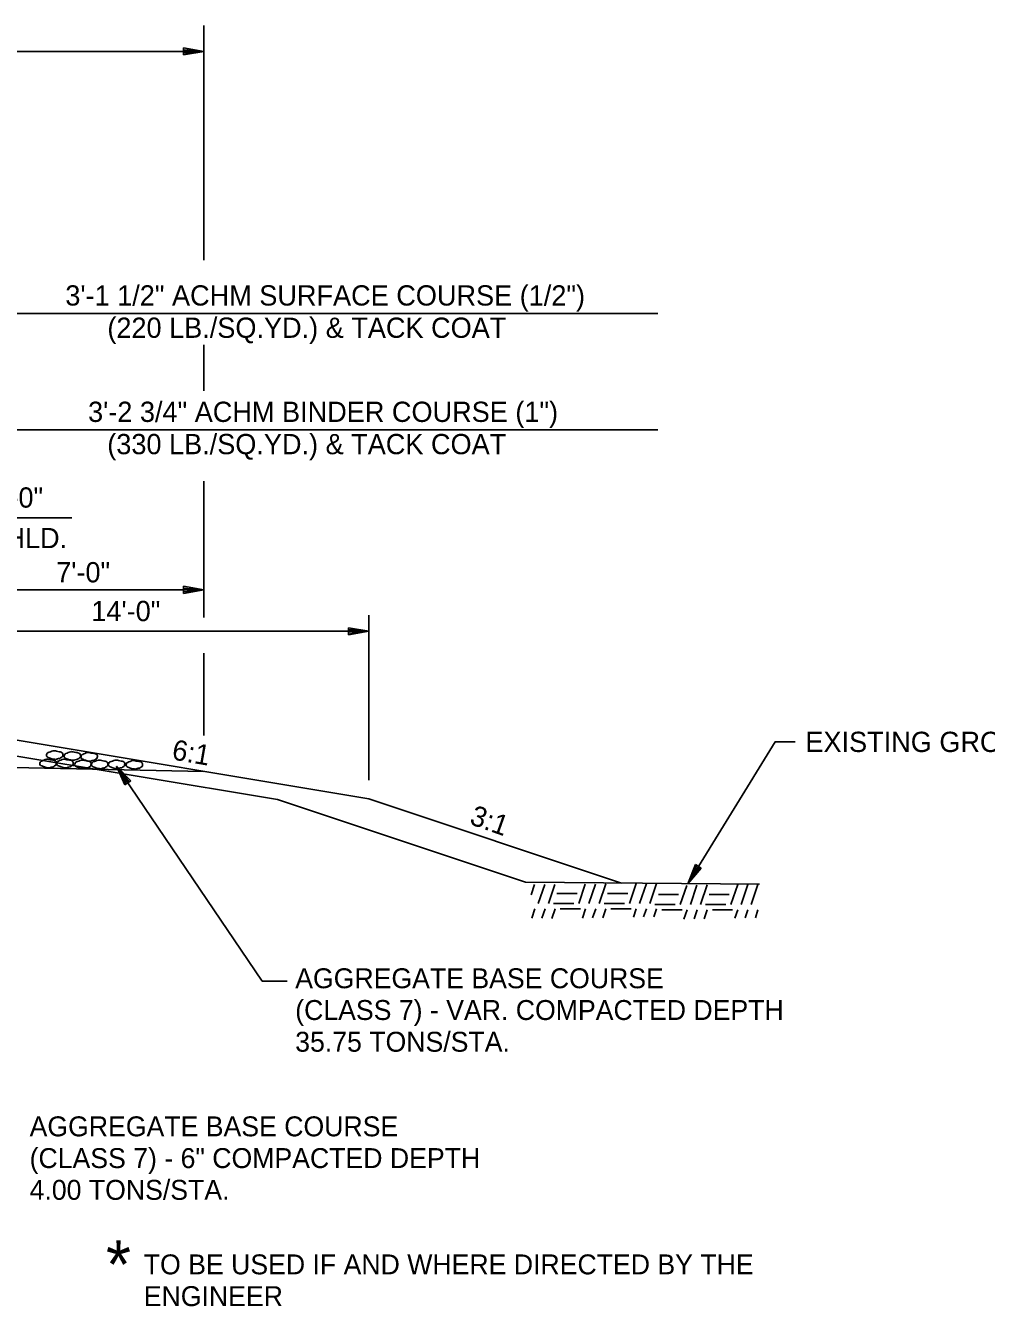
# Model space of a CAD drawing. Extents: x 1461570 to 1461697, y 1686711 to 1686957.
# Drawn here: x 1461621.58 to 1461650.03, y 1686769.49 to 1686807.42 of the extents above; entities that cross this region are included whole.
import ezdxf

# ---------------------------------------------------------------- set-up
doc = ezdxf.new("R2010")
doc.units = 0
for name, color, linetype in [('1', 7, 'Continuous'), ('10', 7, 'Continuous'), ('19', 7, 'Continuous'), ('20', 7, 'Continuous'), ('42', 7, 'Continuous'), ('Default', 7, 'Continuous'), ('Level 9', 7, 'Continuous'), ('R_Draft', 7, 'Continuous')]:
    doc.layers.add(name, color=color, linetype=linetype)

# ---------------------------------------------------------------- blocks, each defined once
blk = doc.blocks.new('ROCKS')
at = {"layer": '1'}
blk.add_spline([(0.013, 0.06), (0.053, 0.053), (0.107, 0.033), (0.133, 0.013), (0.133, -0.007), (0.12, -0.033), (0.107, -0.04), (0.073, -0.053), (0.033, -0.067), (0.013, -0.067), (-0.02, -0.06), (-0.06, -0.053), (-0.087, -0.047), (-0.113, -0.02), (-0.113, -0.007), (-0.107, 0.02), (-0.087, 0.033), (-0.067, 0.047), (-0.033, 0.053), (-0.02, 0.06), (0.013, 0.06)], degree=3, dxfattribs=at)

msp = doc.modelspace()

# ---------------------------------------------------------------- linework, layer by layer
at = {"layer": '19'}
for p, q in [((1461626.253, 1686790.605), (1461626.253, 1686790.815)), ((1461626.253, 1686790.815), (1461626.853, 1686790.71)), ((1461626.253, 1686790.76), (1461626.693, 1686790.725)), ((1461626.853, 1686790.71), (1461626.253, 1686790.605)), ((1461626.693, 1686790.695), (1461626.253, 1686790.655)), ((1461619.738, 1686786.521), (1461631.738, 1686784.521)), ((1461616.654, 1686785.539), (1461626.853, 1686785.335)), ((1461628.584, 1686779.122), (1461624.268, 1686785.492)), ((1461624.513, 1686784.936), (1461624.268, 1686785.492)), ((1461624.268, 1686785.492), (1461624.688, 1686785.051)), ((1461624.554, 1686784.964), (1461624.343, 1686785.35)), ((1461624.366, 1686785.366), (1461624.642, 1686785.024)), ((1461624.688, 1686785.051), (1461624.513, 1686784.936)), ((1461639.219, 1686782.027), (1461631.738, 1686784.521)), ((1461641.186, 1686782.01), (1461641.41, 1686782.576)), ((1461641.587, 1686782.467), (1461641.186, 1686782.01)), ((1461641.26, 1686782.151), (1461641.453, 1686782.544)), ((1461641.547, 1686782.488), (1461641.283, 1686782.139)), ((1461641.41, 1686782.576), (1461641.587, 1686782.467)), ((1461636.377, 1686782.052), (1461643.307, 1686781.991)), ((1461629.321, 1686779.122), (1461628.584, 1686779.122))]:
    msp.add_line(p, q, dxfattribs=at)
msp.add_lwpolyline([(1461644.369, 1686786.209), (1461643.769, 1686786.209), (1461641.186, 1686782.01)], dxfattribs=at)
at = {"layer": '20'}
for p, q in [((1461626.853, 1686800.472), (1461626.853, 1686807.418)), ((1461586.622, 1686806.655), (1461626.853, 1686806.655)), ((1461626.253, 1686806.76), (1461626.253, 1686806.55)), ((1461626.853, 1686806.655), (1461626.253, 1686806.76)), ((1461626.693, 1686806.67), (1461626.253, 1686806.705)), ((1461626.253, 1686806.55), (1461626.853, 1686806.655)), ((1461626.253, 1686806.6), (1461626.693, 1686806.64)), ((1461619.864, 1686798.892), (1461640.297, 1686798.892)), ((1461626.853, 1686796.602), (1461626.853, 1686797.968)), ((1461619.969, 1686795.446), (1461640.297, 1686795.446)), ((1461626.853, 1686789.893), (1461626.853, 1686793.93)), ((1461631.738, 1686785.076), (1461631.738, 1686789.958)), ((1461631.138, 1686789.589), (1461631.138, 1686789.379)), ((1461631.738, 1686789.484), (1461631.138, 1686789.589)), ((1461631.578, 1686789.499), (1461631.138, 1686789.534)), ((1461631.138, 1686789.379), (1461631.738, 1686789.484)), ((1461631.138, 1686789.429), (1461631.578, 1686789.469)), ((1461626.853, 1686786.399), (1461626.853, 1686788.836))]:
    msp.add_line(p, q, dxfattribs=at)
at = {"layer": '42'}
for p, q in [((1461622.946, 1686792.846), (1461617.732, 1686792.845)), ((1461631.738, 1686789.484), (1461617.738, 1686789.484)), ((1461636.547, 1686781.68), (1461636.649, 1686781.986)), ((1461636.76, 1686781.419), (1461636.948, 1686781.984)), ((1461637.06, 1686781.419), (1461637.247, 1686781.982)), ((1461637.96, 1686781.419), (1461638.151, 1686781.991)), ((1461638.26, 1686781.419), (1461638.453, 1686781.998)), ((1461638.56, 1686781.419), (1461638.755, 1686782.004)), ((1461639.46, 1686781.419), (1461639.66, 1686782.019)), ((1461639.507, 1686782.019), (1461639.51, 1686782.019)), ((1461639.76, 1686781.419), (1461639.96, 1686782.019)), ((1461640.06, 1686781.419), (1461640.26, 1686782.019)), ((1461640.965, 1686781.389), (1461641.156, 1686781.961)), ((1461641.265, 1686781.389), (1461641.458, 1686781.967)), ((1461641.565, 1686781.389), (1461641.76, 1686781.973)), ((1461642.465, 1686781.389), (1461642.665, 1686781.989)), ((1461642.512, 1686781.989), (1461642.515, 1686781.989)), ((1461642.765, 1686781.389), (1461642.965, 1686781.989)), ((1461643.065, 1686781.389), (1461643.265, 1686781.989)), ((1461637.31, 1686781.719), (1461637.91, 1686781.719)), ((1461638.81, 1686781.719), (1461639.41, 1686781.719)), ((1461640.315, 1686781.689), (1461640.915, 1686781.689)), ((1461641.815, 1686781.689), (1461642.415, 1686781.689)), ((1461636.566, 1686780.987), (1461636.66, 1686781.269)), ((1461636.865, 1686780.985), (1461636.96, 1686781.269)), ((1461637.164, 1686780.982), (1461637.26, 1686781.269)), ((1461637.21, 1686781.419), (1461637.81, 1686781.419)), ((1461637.41, 1686781.269), (1461638.01, 1686781.269)), ((1461638.067, 1686780.99), (1461638.16, 1686781.269)), ((1461638.369, 1686780.996), (1461638.46, 1686781.269)), ((1461638.671, 1686781.002), (1461638.76, 1686781.269)), ((1461638.71, 1686781.419), (1461639.31, 1686781.419)), ((1461638.91, 1686781.269), (1461639.46, 1686781.269)), ((1461639.46, 1686781.269), (1461639.51, 1686781.269)), ((1461639.577, 1686781.021), (1461639.66, 1686781.269)), ((1461639.879, 1686781.027), (1461639.96, 1686781.269)), ((1461640.181, 1686781.033), (1461640.26, 1686781.269)), ((1461640.215, 1686781.389), (1461640.815, 1686781.389)), ((1461640.415, 1686781.239), (1461641.015, 1686781.239)), ((1461641.072, 1686780.959), (1461641.165, 1686781.239)), ((1461641.374, 1686780.965), (1461641.465, 1686781.239)), ((1461641.676, 1686780.971), (1461641.765, 1686781.239)), ((1461641.715, 1686781.389), (1461642.315, 1686781.389)), ((1461641.915, 1686781.239), (1461642.465, 1686781.239)), ((1461642.465, 1686781.239), (1461642.515, 1686781.239)), ((1461642.583, 1686780.99), (1461642.665, 1686781.239)), ((1461642.885, 1686780.996), (1461642.965, 1686781.239)), ((1461643.187, 1686781.003), (1461643.265, 1686781.239))]:
    msp.add_line(p, q, dxfattribs=at)
at = {"layer": 'Level 9'}
msp.add_line((1461626.853, 1686790.71), (1461619.738, 1686790.71), dxfattribs=at)
at = {"layer": 'R_Draft'}
for p, q in [((1461629.039, 1686784.498), (1461617.238, 1686786.465)), ((1461636.377, 1686782.052), (1461629.039, 1686784.498))]:
    msp.add_line(p, q, dxfattribs=at)

# ---------------------------------------------------------------- block references
at = {"layer": '1', "xscale": 1.968733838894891, "yscale": 1.968733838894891, "rotation": 180}
for p in [(1461622.263, 1686785.563), (1461622.455, 1686785.813), (1461622.761, 1686785.563), (1461622.98, 1686785.786), (1461623.292, 1686785.537), (1461623.478, 1686785.76), (1461623.791, 1686785.537), (1461624.289, 1686785.537), (1461624.814, 1686785.524)]:
    msp.add_blockref('ROCKS', p, dxfattribs=at)

# ---------------------------------------------------------------- texts
at = {"layer": '10'}
for s, height, rotation, p in [('*', 1.422, 359.9954, (1461623.955, 1686770.026)), ('TO BE USED IF AND WHERE DIRECTED BY THE ', 0.59001, 360, (1461625.075, 1686770.442)), ('ENGINEER', 0.59, 360, (1461625.075, 1686769.502))]:
    msp.add_text(s, height=height, rotation=rotation, dxfattribs=at).set_placement(p)
at = {"layer": '19'}
for s, p in [('2\'-0"', (1461620.497, 1686793.145)), ('SHLD.', (1461620.443, 1686791.945)), ('7\'-0"', (1461622.481, 1686790.932)), ('14\'-0"', (1461623.522, 1686789.784))]:
    msp.add_text(s, height=0.6, dxfattribs=at).set_placement(p)
for s, height, rotation, p in [('6:1', 0.6, 350.1584, (1461625.884, 1686785.694)), ('3:1', 0.6, 340.4943, (1461634.693, 1686783.785)), ('AGGREGATE BASE COURSE', 0.59001, 360, (1461629.56, 1686778.914)), ('(CLASS 7) - VAR. COMPACTED DEPTH', 0.59001, 360, (1461629.56, 1686777.974)), ('35.75 TONS/STA.', 0.59001, 360, (1461629.56, 1686777.034)), ('AGGREGATE BASE COURSE', 0.59001, 360, (1461621.694, 1686774.529)), ('(CLASS 7) - 6" COMPACTED DEPTH', 0.59001, 360, (1461621.694, 1686773.589)), ('4.00 TONS/STA.', 0.59001, 360, (1461621.694, 1686772.649))]:
    msp.add_text(s, height=height, rotation=rotation, dxfattribs=at).set_placement(p)
at = {"layer": 'Default'}
for s, p in [('3\'-1 1/2" ACHM SURFACE COURSE (1/2")', (1461622.752, 1686799.129)), ('(220 LB./SQ.YD.) & TACK COAT', (1461623.997, 1686798.173)), ('3\'-2 3/4" ACHM BINDER COURSE (1")', (1461623.425, 1686795.683)), ('(330 LB./SQ.YD.) & TACK COAT', (1461623.994, 1686794.727))]:
    msp.add_text(s, height=0.60001, dxfattribs=at).set_placement(p)
at = {"layer": 'R_Draft'}
msp.add_text('EXISTING GROUND', height=0.6, dxfattribs=at).set_placement((1461644.669, 1686785.909))

doc.saveas('drawing.dxf')
